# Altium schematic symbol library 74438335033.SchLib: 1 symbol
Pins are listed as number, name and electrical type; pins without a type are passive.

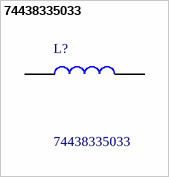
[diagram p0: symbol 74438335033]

## 74438335033
designator L?
WE-MAPI SMD Shielded Power Inductor, 3015, 3.3uH; Manufacturer_Name: Wurth Elektronik; Geometry.Height: 1.5mm
footprint INDC3030X150N
pins: 1, 2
